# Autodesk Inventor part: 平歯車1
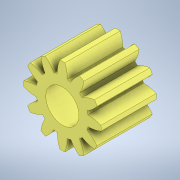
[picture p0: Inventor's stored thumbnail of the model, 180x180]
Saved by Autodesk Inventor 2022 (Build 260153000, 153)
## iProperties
CustomPartVersion: 1
Created: 2024-12
Part Number: 平歯車1
Material: Steel
Document SubType Name: Modeling
Designer: jsat7
Categories: <?xml version="1.0" encoding="UTF-16"?> <MemberInstance><Categories><FamilyTemplate><FamilyTemplateParameter ValueType="xs:double" Id="1" ObjectReferenceKey="da
Density: 1 g/cm^3
Appearance: Steel
Author: jsat7
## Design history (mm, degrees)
sketch "Sketch1"
  geometry: C1 r 3.5 at (0, 0)
  constraints: 1 centre point
  dimensions: "d0" = 7 diameter of C1 (= da_da)
extrude "Extrusion1" new body sketch "Sketch1" distance "d1" = 5 (= da_b); taper "d2" = 0 deg
workplane "Work Plane2"
sketch "Sketch2"
  geometry: C1 r 3.5 at (0, 0) reference; C2 r 3 at (0, 0)
  constraints: 1 centre point, 1 coincident
  dimensions: "d3" = 6 diameter of C2 (= da_d)
feature "ピッチ円直径" sketch "Sketch2" dims "d4" = 10, "d5" = 0
workplane "Work Plane8"
workplane "Work Plane9"
feature "平歯車" dims "da_b" = 5, "da_d" = 6, "da_aw" = 11.25, "da_da" = 7, "da_df" = 4.75, "da_dw" = 6, angle "da_beta" = 0 deg, "da_lefttooth" = 0, "da_righttooth" = 0
sketch "スケッチ3"
  geometry: C1 r 1.5 at (0, 0); 1 further point
  constraints: 1 centre point, 1 coincident
  dimensions: "d49" = 3 diameter of C1
extrude "押し出し2" cut sketch "スケッチ3" distance "d50" = 10; taper "d51" = 0 deg
body "Solid1"
body "Srf1"
other parameters: "d16" = 11.25 (= da_aw), "d17" = 0, "d34" = 15 deg (computed from da_z), "d39" = 0, "d41" = 0, "d43" = 11.25 (= da_aw), "d46" = 11.25 (= da_aw), "d47" = 0, "d48" = 0
